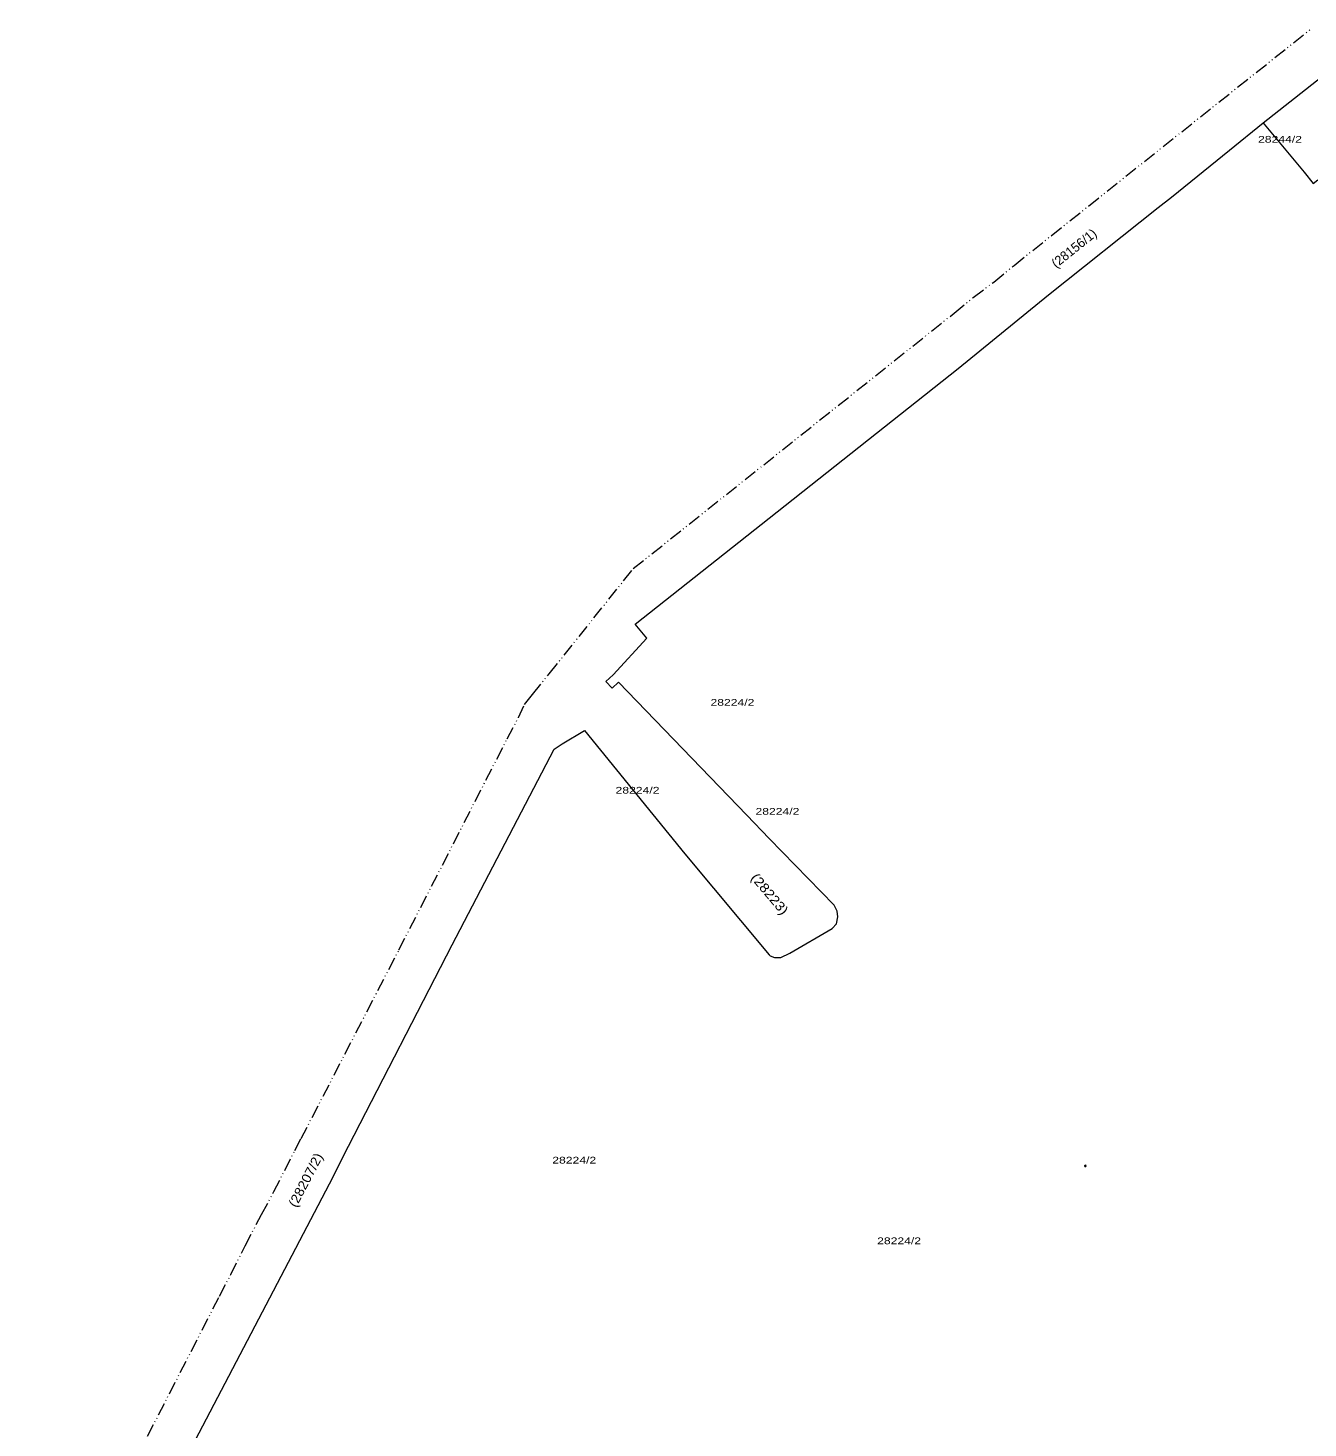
# Model space of a CAD drawing. Extents: x 650553 to 652508, y 239277 to 241647.
# Drawn here: x 650714 to 651208, y 241007 to 241547 of the extents above; entities that cross this region are included whole.
import ezdxf

# ---------------------------------------------------------------- set-up
doc = ezdxf.new("R2010")
doc.units = 0
doc.header["$PDMODE"] = 32
doc.header["$PDSIZE"] = 0.5
doc.linetypes.add('DASH_DOUBLE_DOT', pattern=[9.2, 5, -1.2, 0.3, -1.2, 0.3, -1.2])
for name, color, linetype in [('19', 7, 'Continuous'), ('20', 7, 'Continuous'), ('6', 7, 'Continuous')]:
    doc.layers.add(name, color=color, linetype=linetype)
for name, color, linetype, lineweight in [('3', 7, 'Continuous', 13), ('5', 7, 'Continuous', 13), ('52', 7, 'DASH_DOUBLE_DOT', 13)]:
    doc.layers.add(name, color=color, linetype=linetype, lineweight=lineweight)

msp = doc.modelspace()

# ---------------------------------------------------------------- linework, layer by layer
at = {"layer": '3'}
for points in [[(651190.84, 241510.5), (651225.94, 241538.26), (651228.47, 241538.01), (651247.73, 241515.82)], [(650713.699, 240878.214), (650830.17, 241100.87), (650837.49, 241115.31), (650877.519, 241193.16), (650916.9, 241268.638), (650919.993, 241270.775), (650928.674, 241275.939), (650967.392, 241228.263), (651000, 241189.31), (651000.37, 241188.88), (651002.03, 241188.2), (651004.52, 241188.24), (651007.93, 241189.92), (651024.31, 241199.38), (651026.01, 241201.28), (651026.52, 241203.87), (651026.33, 241206.11), (651025.05, 241208.42), (651000, 241234.11), (650991.426, 241243.216), (650941.804, 241294.592), (650939.345, 241292.27), (650936.959, 241294.851), (650939.802, 241297.399), (650952.785, 241311.482), (650948.29, 241316.9), (651000, 241357.88), (651072.96, 241415.72), (651107.92, 241444.09), (651150.29, 241477.89), (651155.48, 241481.9), (651177.85, 241500), (651190.84, 241510.5)]]:
    msp.add_lwpolyline(points, dxfattribs=at)
at = {"layer": '5'}
msp.add_line((651199.56, 241500), (651206.68, 241491.44), dxfattribs=at)
for points in [[(651190.84, 241510.5), (651191.255, 241510), (651199.56, 241500)], [(651206.68, 241491.44), (651210.12, 241487.14), (651211.96, 241488.57)]]:
    msp.add_lwpolyline(points, dxfattribs=at)
at = {"layer": '52'}
msp.add_lwpolyline([(650722.084, 240929.73), (650787.671, 241057.451), (650792.055, 241065.789), (650797.577, 241076.93), (650803.912, 241088.98), (650808.727, 241097.798), (650816.77, 241113.748), (650819.208, 241118.275), (650857.008, 241191.194), (650898.803, 241272.671), (650903.184, 241280.906), (650905.437, 241285.861), (650908.619, 241289.817), (650915.057, 241297.807), (650947.516, 241338.395), (651071.42, 241437.025), (651078.776, 241443.079), (651086.741, 241449.066), (651094.598, 241455.508), (651209.715, 241547.174)], dxfattribs=at)
at = {"layer": '6'}
msp.add_point((651122.128, 241107.726), dxfattribs=at)

# ---------------------------------------------------------------- texts
at = {"layer": '19'}
msp.add_text('(28156/1)', height=3.6, rotation=38.581, dxfattribs=at).set_placement((651110.835, 241454.301))
for s, rotation, width, p in [('(28223)', 310.295, 1.15, (650992.669, 241218.875)), ('(28207/2)', 62.433, 1.1, (650817.3, 241091.411))]:
    msp.add_text(s, height=3.6, rotation=rotation, dxfattribs=dict(at, width=width)).set_placement(p)
at = {"layer": '20', "width": 1.35}
for s, p in [('28244/2', (651188.853, 241502.893)), ('28224/2', (650977.333, 241285.431)), ('28224/2', (650940.667, 241251.505)), ('28224/2', (650994.72, 241243.353)), ('28224/2', (650916.221, 241108.645)), ('28224/2', (651041.709, 241077.498))]:
    msp.add_text(s, height=2.6, dxfattribs=at).set_placement(p)

doc.saveas('drawing.dxf')
